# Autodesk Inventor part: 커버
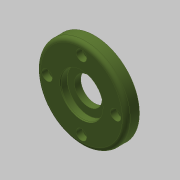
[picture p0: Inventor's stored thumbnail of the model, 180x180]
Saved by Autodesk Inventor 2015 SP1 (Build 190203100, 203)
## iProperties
Created: 2016-06
Part Number: 커버
Material: 알루미늄 6061
Document SubType Name: Modeling
Designer: mduedu
Density: 2.71 g/cm^3
Appearance: 올리브 녹색
Author: mduedu
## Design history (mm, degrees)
sketch "스케치1"
  geometry: C1 r 34 at (0, 0); 1 further point
  constraints: 1 centre point, 1 coincident
  dimensions: "d0" = 68 diameter of C1
extrude "돌출1" new body sketch "스케치1" distance "d2" = 10; taper "d3" = 0 deg
sketch "스케치2"
  geometry: C1 r 21 at (0, 0); 1 further point
  constraints: 1 centre point, 1 coincident
  dimensions: "d4" = 42 diameter of C1
extrude "돌출2" join sketch "스케치2" distance "d6" = 3; taper "d7" = 0 deg
fillet "모깎기1" dims "d8" = 3
hole "구멍1" diameter "d11" = 35; stored, may be unused: countersink angle "d15" = 90 deg, drill point angle "d17" = 0 deg; dims "d9" = 10, "d10" = 10, "d12" = 6, "d13" = 4, "d14" = 2, "d16" = 3
hole "구멍2" diameter "d20" = 32; stored, may be unused: countersink angle "d24" = 90 deg, drill point angle "d26" = 0 deg; dims "d21" = 6, "d22" = 4, "d23" = 2, "d25" = 5.2, "d46" = 10, "d47" = 10
hole "구멍3" diameter "d29" = 21; stored, may be unused: countersink angle "d33" = 90 deg, drill point angle "d35" = 0 deg; dims "d27" = 10, "d28" = 10, "d30" = 6, "d31" = 4, "d32" = 2, "d34" = 5
fillet "모깎기2" dims "d36" = 3
fillet "모깎기3" dims "d37" = 0.1
chamfer "모따기1" distance "d38" = 0.75; stored, may be unused: second distance "d39" = 2, angle "d40" = 30 deg
chamfer "모따기2" distance "d42" = 0.5; stored, may be unused: second distance "d43" = 2, angle "d44" = 30 deg
sketch "스케치3" dims "d48" = 52
  geometry: 6 further points
  constraints: 2 vertical alignment, 1 coincident, 7 other
  dimensions: "d51" = 360 deg dimension on point (0, 0) point (0, 26) (derived)
sketch "스케치4"
  geometry: 4 further points
hole "구멍4" sketch "스케치4" at (0, 26), (-26, 0), (0, -26), (26, 0) diameter "d53" = 4.5; stored, may be unused: countersink angle "d57" = 90 deg, drill point angle "d59" = 0 deg; dims "d54" = 6, "d55" = 8, "d56" = 4.6, "d58" = 8
node "솔리드1"
